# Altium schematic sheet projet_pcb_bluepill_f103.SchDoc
size A2
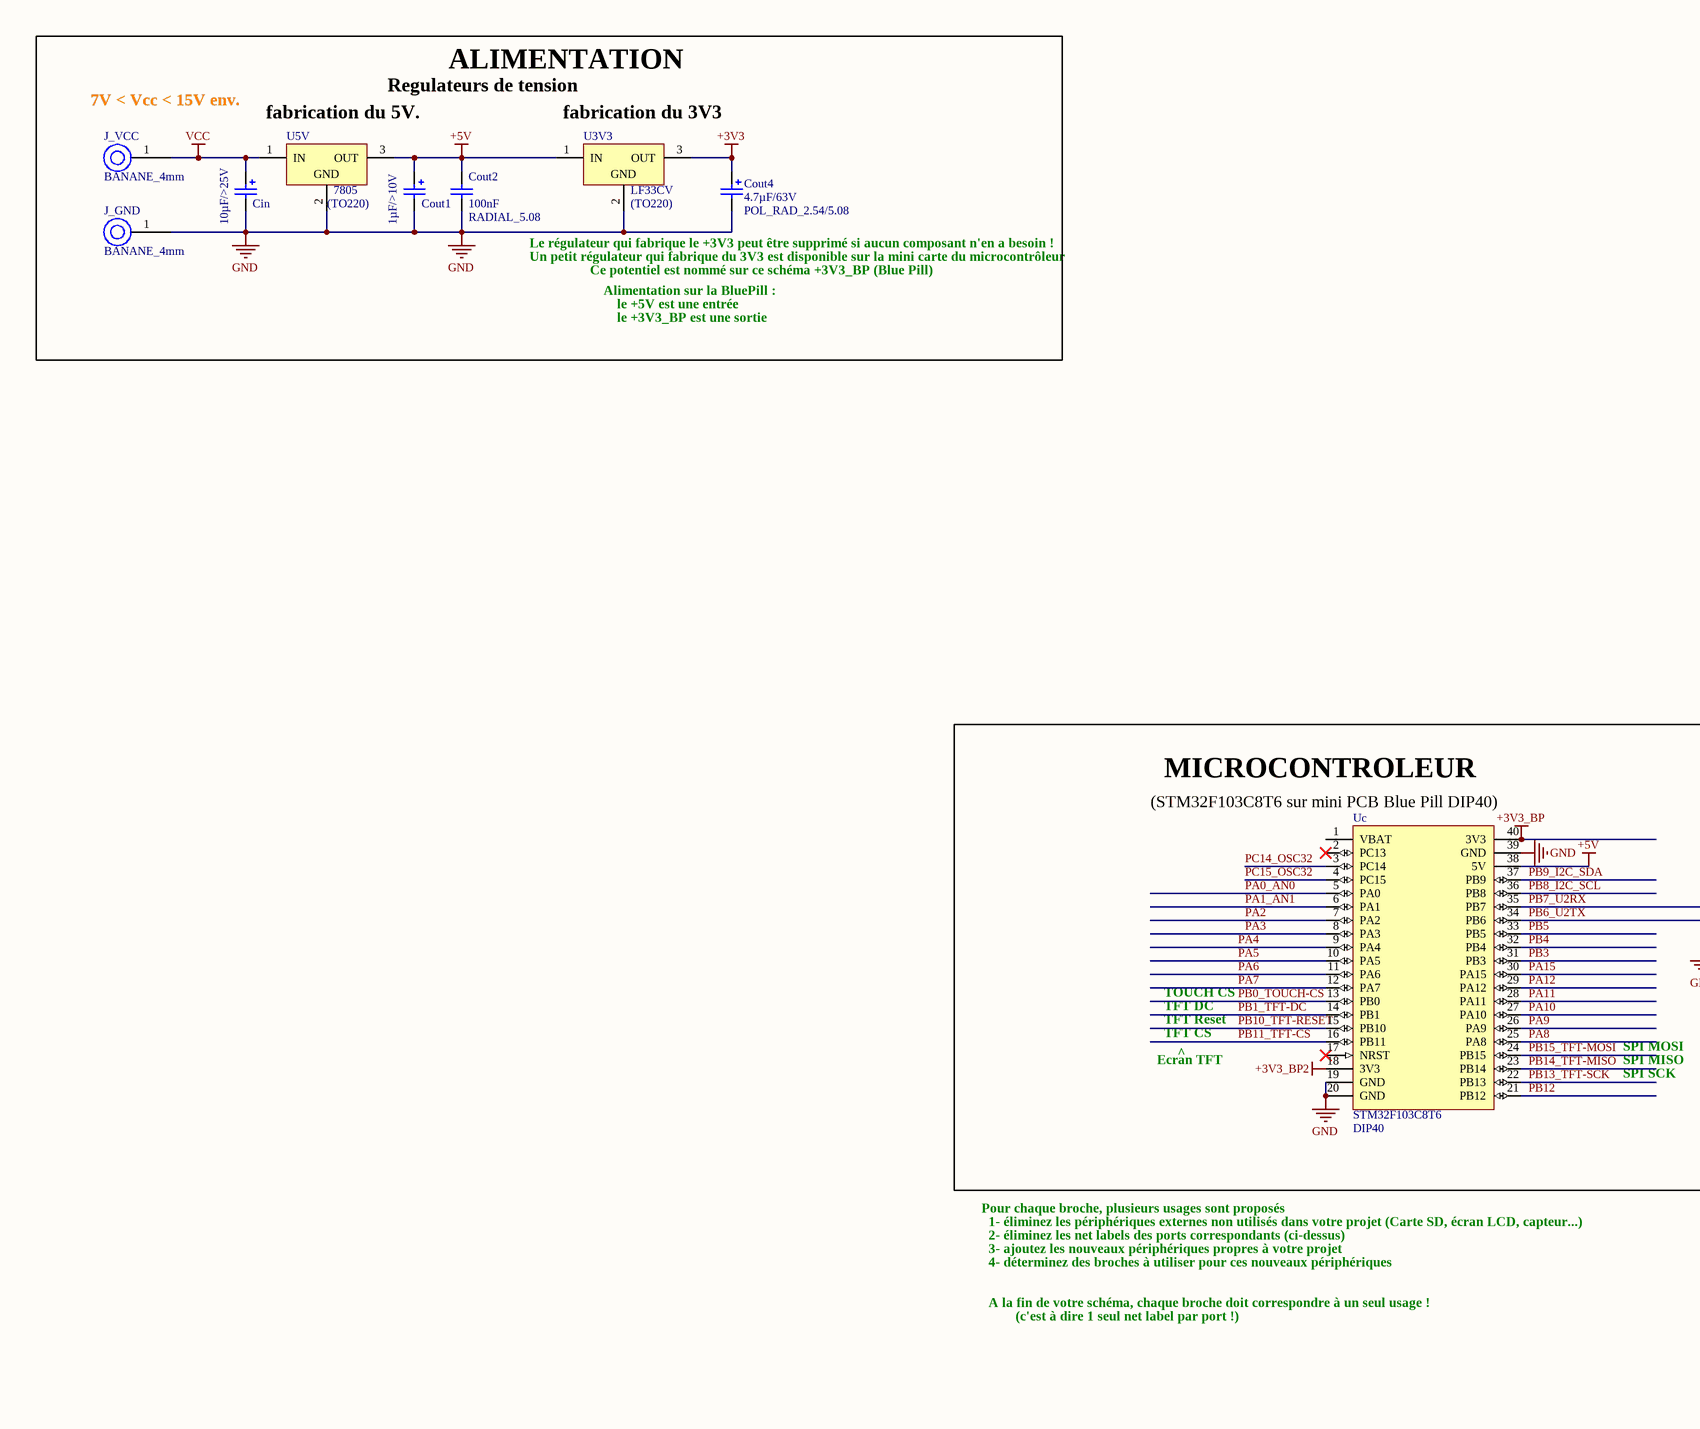
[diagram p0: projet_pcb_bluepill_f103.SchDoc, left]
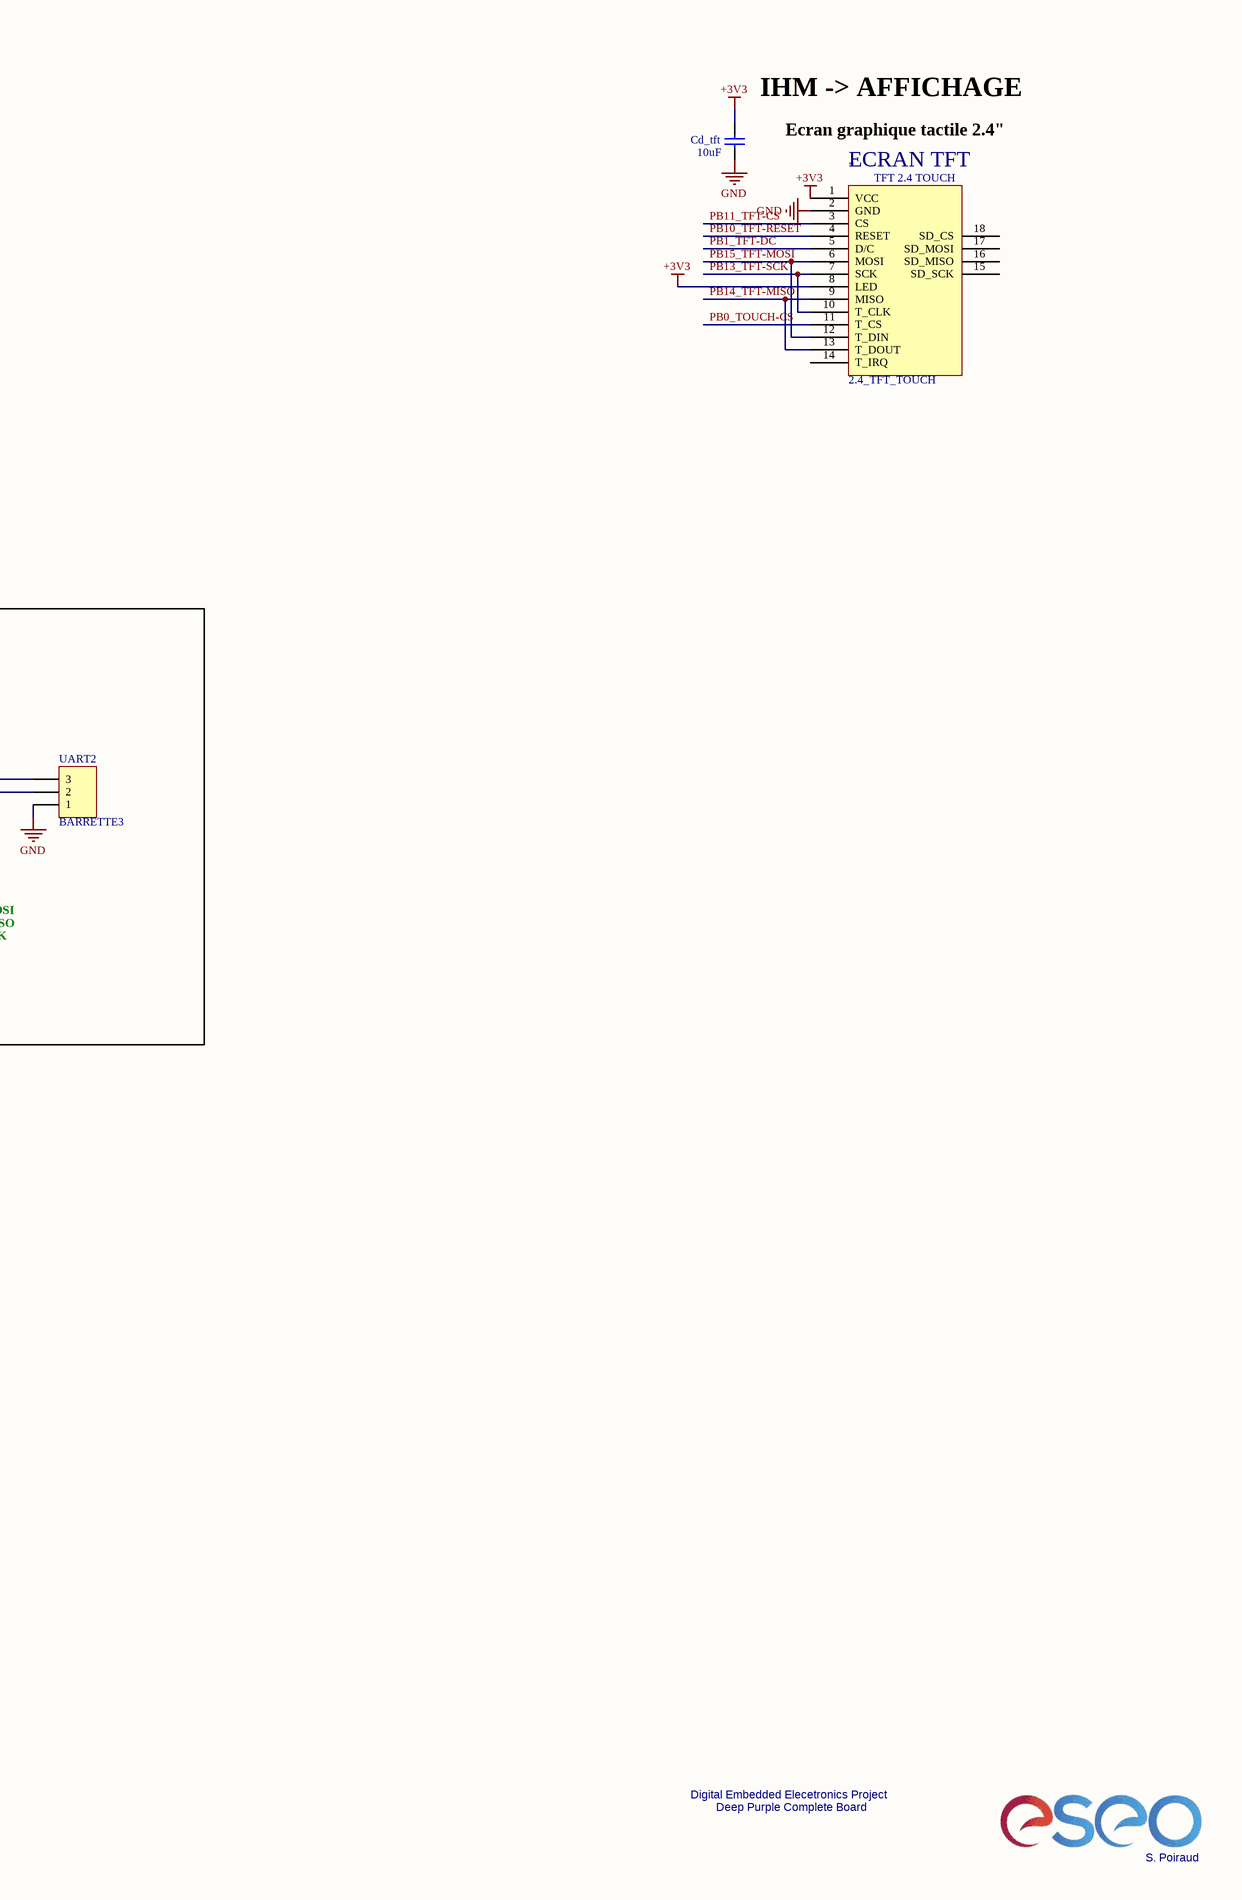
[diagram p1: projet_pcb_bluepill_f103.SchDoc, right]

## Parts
*  2.4_TFT_TOUCH  [2.4_TFT_TOUCH]
Cd_tft  10uF  [CONDENSATEUR_POLARISE_ELECTROLYTIQUE_RADIAL_2.54/5.08]
Cin  value 10µF/>25V  [CONDENSATEUR_POLARISE_ELECTROLYTIQUE_RADIAL_2.0/5.08]  (hidden comment: CONDENSATEUR_POL_ELECTROLY_RAD_2.0/5.08)
Cout1  value 1µF/>10V  [CONDENSATEUR_POLARISE_ELECTROLYTIQUE_RADIAL_2.0/5.08]  (hidden comment: CONDENSATEUR_POL_ELECTROLY_RAD_2.0/5.08)
Cout2  value 100nF  Type: RADIAL_5.08  [CONDENSATEUR_CERAMIQUE_RADIAL_5.08]  (hidden comment: CONDENSATEUR_CER_RAD_5.08)
Cout4  value 4.7µF/63V  Type: POL_RAD_2.54/5.08  [CONDENSATEUR_POLARISE_ELECTROLYTIQUE_RADIAL_2.54/5.08]  (hidden comment: CONDENSATEUR_POL_ELECTROLY_RAD_2.54/5.08)
J_GND  Type: BANANE_4mm  [DOUILLE_BANANE_4mm]  (hidden comment: DOUILLE BANANE 4mm)
J_VCC  Type: BANANE_4mm  [DOUILLE_BANANE_4mm]  (hidden comment: DOUILLE BANANE 4mm)
U3V3  Type: LF33CV  Package: (TO220)  [REGULATEUR_TO220_78XX]  (hidden comment: REGULATEUR_TO220_78XX)
U5V  Type: 7805  Package: (TO220)  [REGULATEUR_TO220_78XX]  (hidden comment: REGULATEUR_TO220_78XX)
UART2  BARRETTE3  [HDR1X3]
Uc  Type: STM32F103C8T6  Package: DIP40  [STM32F103C8T6_DIP40]  (hidden comment: STM32F103C8T6/PCB_DIP40)

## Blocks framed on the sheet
ALIMENTATION: Cin Cout1 Cout2 Cout4 J_GND J_VCC U3V3 U5V
MICROCONTROLEUR: UART2 Uc

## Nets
+3V3: *.1(VCC) *.8(LED) Cd_tft.1 Cout4.1 U3V3.3(OUT)
+3V3_BP: Uc.40(3V3)
+3V3_BP2: Uc.18(3V3)
+5V: Cout1.1 Cout2.2 U3V3.1(IN) U5V.3(OUT) Uc.38(5V)
GND: *.2(GND) Cd_tft.2 Cin.2 Cout1.2 Cout2.1 Cout4.2 J_GND.1 U3V3.2(GND) U5V.2(GND) UART2.1 Uc.19(GND) Uc.20(GND) Uc.39(GND)
VCC: Cin.1 J_VCC.1 U5V.1(IN)
PA0_AN0: Uc.5(PA0)
PA1_AN1: Uc.6(PA1)
PA2: Uc.7(PA2)
PA3: Uc.8(PA3)
PA4: Uc.9(PA4)
PA5: Uc.10(PA5)
PA6: Uc.11(PA6)
PA7: Uc.12(PA7)
PA8: Uc.25(PA8)
PA9: Uc.26(PA9)
PA10: Uc.27(PA10)
PA11: Uc.28(PA11)
PA12: Uc.29(PA12)
PA15: Uc.30(PA15)
PB0_TOUCH-CS: *.11(T_CS) Uc.13(PB0)
PB1_TFT-DC: *.5(D/C) Uc.14(PB1)
PB3: Uc.31(PB3)
PB4: Uc.32(PB4)
PB5: Uc.33(PB5)
PB6_U2TX: UART2.2 Uc.34(PB6)
PB7_U2RX: UART2.3 Uc.35(PB7)
PB8_I2C_SCL: Uc.36(PB8)
PB9_I2C_SDA: Uc.37(PB9)
PB10_TFT-RESET: *.4(RESET) Uc.15(PB10)
PB11_TFT-CS: *.3(CS) Uc.16(PB11)
PB12: Uc.21(PB12)
PB13_TFT-SCK: *.7(SCK) *.10(T_CLK) Uc.22(PB13)
PB14_TFT-MISO: *.9(MISO) *.13(T_DOUT) Uc.23(PB14)
PB15_TFT-MOSI: *.6(MOSI) *.12(T_DIN) Uc.24(PB15)
PC14_OSC32: Uc.3(PC14)
PC15_OSC32: Uc.4(PC15)

Not connected (* = marked no-connect by the designer): * 14(T_IRQ) 15(SD_SCK) 16(SD_MISO) 17(SD_MOSI) 18(SD_CS); Uc 1(VBAT) 2(PC13)* 17(NRST)*

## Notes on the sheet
- 7V < Vcc < 15V env.
- Regulateurs de tension
- (near U5V) fabrication du 5V.
- (near U3V3) fabrication du 3V3
- Le régulateur qui fabrique le +3V3 peut être supprimé si aucun composant n'en a besoin !
- (near Cd_tft) IHM -> AFFICHAGE
- Ecran graphique tactile 2.4"
- Un petit régulateur qui fabrique du 3V3 est disponible sur la mini carte du microcontrôleur
- Ce potentiel est nommé sur ce schéma +3V3_BP (Blue Pill)
- Alimentation sur la BluePill :
- le +5V est une entrée
- (near *) ECRAN TFT
- le +3V3_BP est une sortie
- (near Uc) (STM32F103C8T6 sur mini PCB Blue Pill DIP40)
- TOUCH CS
- TFT DC
- TFT Reset
- TFT CS
- ^
- SPI MOSI
- Ecran TFT
- SPI SCK
- SPI MISO
- Pour chaque broche, plusieurs usages sont proposés
- 1- éliminez les périphériques externes non utilisés dans votre projet (Carte SD, écran LCD, capteur...)
- 2- éliminez les net labels des ports correspondants (ci-dessus)
- 3- ajoutez les nouveaux périphériques propres à votre projet
- 4- déterminez des broches à utiliser pour ces nouveaux périphériques
- A la fin de votre schéma, chaque broche doit correspondre à un seul usage !
- (c'est à dire 1 seul net label par port !)
- Digital Embedded Elecetronics Project
- Deep Purple Complete Board
- S. Poiraud

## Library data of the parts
Cd_tft = Condensateur: Capacitor
Cin Cout1 = CONDENSATEUR_POL_ELECTROLY_RAD_2.0/5.08: CONDENSATEUR POLARISE ELECTROLYTIQUE RADIAL 2.0/5.08
Cout2 = CONDENSATEUR_CER_RAD_5.08: CONDENSATEUR TRAVERSANT CERAMIQUE RADIAL 5.08mm
Cout4 = CONDENSATEUR_POL_ELECTROLY_RAD_2.54/5.08: CONDENSATEUR POLARISE ELECTROLYTIQUE RADIAL 2.54/5.08
J_GND J_VCC = DOUILLE_BANANE_4mm: DOUILLE BANANE 4 mm
U3V3 U5V = REGULATEUR_TO220_78XX: REGULATEUR DE TENSION POSITIVE 78XX BOITIER TO220
UART2 = BARRETTE3: Header, 3-Pin
Uc = STM32F103C8T6/PCB_DIP40: MICROCONTROLEUR 32 BITS - 72MHz - 34 I/O - 64 KO : FLASH - 20KO RAM - 10 CANAUX A/D 12 BITS - DIP40 - UART, SPI, I2C, USB, CAN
